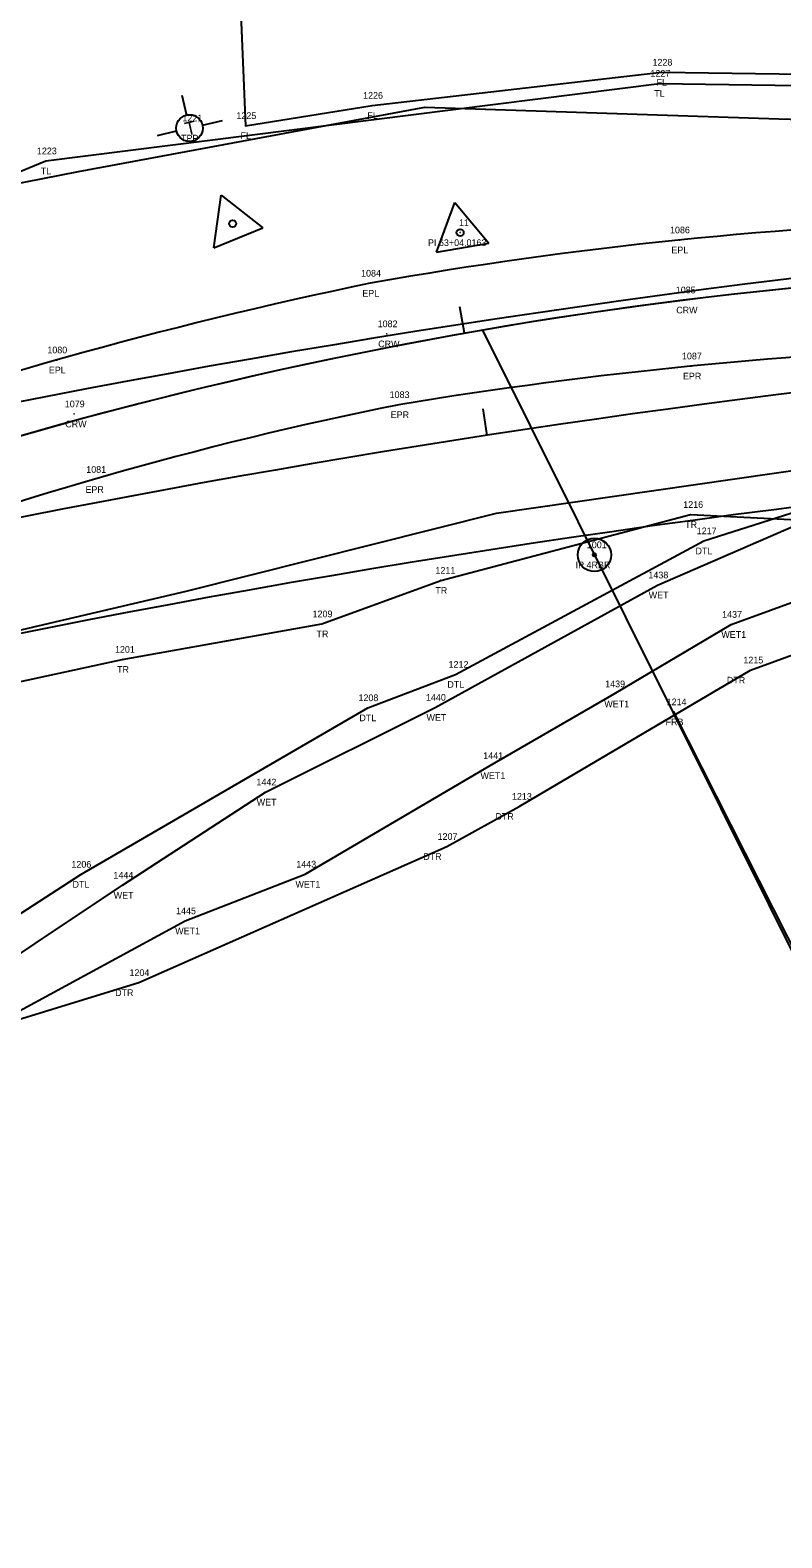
# Model space of a CAD drawing. Extents: x 1964982 to 1970527, y 1116335 to 1119906.
# Drawn here: x 1967915.5 to 1968028, y 1117741.3 to 1117966.8 of the extents above; entities that cross this region are included whole.
import ezdxf

# ---------------------------------------------------------------- set-up
doc = ezdxf.new("R2010")
doc.units = 0
for name, color, linetype in [('RD_EX_DV_Prop', 7, 'Continuous'), ('RD_EX_DV_Prop_txCode', 7, 'Continuous'), ('RD_EX_DV_PropPin', 7, 'Continuous'), ('RD_EX_Fence_Other', 7, 'Continuous'), ('RD_EX_Fence_Other_txCode', 7, 'Continuous'), ('RD_EX_H2O', 7, 'Continuous'), ('RD_EX_H2O_txCode', 7, 'Continuous'), ('RD_EX_H2O_WetLd', 7, 'Continuous'), ('RD_EX_H2O_WetLd_txCode', 7, 'Continuous'), ('RD_EX_Road', 7, 'Continuous'), ('RD_EX_Road_txCode', 7, 'Continuous'), ('RD_EX_RW', 7, 'Continuous'), ('RD_EX_UT', 7, 'Continuous'), ('RD_EX_UT_txCode', 7, 'Continuous'), ('RD_EX_VEG', 7, 'Continuous'), ('RD_EX_VEG_txCode', 7, 'Continuous'), ('RD_HC_CL', 7, 'Continuous'), ('RD_HC_CL_Rel', 7, 'Continuous'), ('RD_HC_Data', 7, 'Continuous'), ('RD_HC_Data_Rel', 7, 'Continuous'), ('RD_HC_Data_Tic', 7, 'Continuous'), ('RD_HC_Data_Tic_Rel', 7, 'Continuous'), ('RD_HC_txCode', 7, 'Continuous'), ('RD_PD_Bridge', 7, 'Continuous'), ('RD_SMD_Locator', 7, 'Continuous'), ('RD_SMD_Misc', 7, 'Continuous')]:
    doc.layers.add(name, color=color, linetype=linetype)

msp = doc.modelspace()

# ---------------------------------------------------------------- linework, layer by layer
at = {"layer": 'RD_EX_DV_Prop'}
msp.add_line((1967983.2, 1117921.94), (1968204.25, 1117478.1), dxfattribs=at)
msp.add_arc((1968094.39, 1117277.53), 653.93, 87.72663, 109.21172, dxfattribs=at)
at = {"layer": 'RD_EX_DV_PropPin'}
for radius in [2.5, 0.25]:
    msp.add_circle((1967999.94, 1117888.32), radius, dxfattribs=at)
at = {"layer": 'RD_EX_Fence_Other'}
msp.add_line((1968047.83, 1117793.64), (1968011.81, 1117864.83), dxfattribs=at)
msp.add_lwpolyline([(1967945.93, 1117995.37), (1967947.71, 1117952.52), (1967966.69, 1117955.54), (1968009.98, 1117960.51), (1968062.77, 1117959.8), (1968105.6, 1117961.86), (1968158.55, 1117958.33), (1968214.15, 1117955.95), (1968422.33, 1117947.89), (1968537.53, 1117942.88)], dxfattribs=at)
at = {"layer": 'RD_EX_H2O'}
for points in [[(1967869.1, 1117825.19), (1967872.82, 1117824.49), (1967892.16, 1117820.53), (1967923.08, 1117840.53), (1967966.02, 1117865.44), (1967979.17, 1117870.44), (1968016.32, 1117890.41), (1968058.49, 1117903.84)], [(1967873.55, 1117813.3), (1967887.27, 1117810.69), (1967931.74, 1117824.33), (1967977.85, 1117844.69), (1967988.67, 1117850.69), (1968023.3, 1117871.08), (1968058.02, 1117883.74)]]:
    msp.add_lwpolyline(points, dxfattribs=at)
at = {"layer": 'RD_EX_H2O_WetLd'}
for points in [[(1967871.9, 1117823.22), (1967882.77, 1117820.95), (1967892.49, 1117817.57), (1967903.12, 1117821.47), (1967929.31, 1117838.9), (1967950.71, 1117852.83), (1967976.12, 1117865.5), (1968009.37, 1117883.81), (1968032.7, 1117893.9)], [(1967873.8, 1117813.35), (1967880.72, 1117811.81), (1967886.54, 1117810.11), (1967895.47, 1117810.58), (1967906.3, 1117816.05), (1967938.67, 1117833.57), (1967956.67, 1117840.55), (1967984.36, 1117856.79), (1968002.89, 1117867.52), (1968020.4, 1117877.91), (1968037.49, 1117884.16)]]:
    msp.add_lwpolyline(points, dxfattribs=at)
at = {"layer": 'RD_EX_Road'}
for centre, radius, start, end in [((1968075.08, 1117320.65), 617.93, 91.49649, 100.12953), ((1968104.91, 1117261.07), 682.09, 101.71624, 109.63962), ((1968080.71, 1117246.52), 673.31, 91.83702, 99.40571), ((1968080.62, 1117362.97), 558.74, 101.3479, 110.7006)]:
    msp.add_arc(centre, radius, start, end, dxfattribs=at)
at = {"layer": 'RD_EX_RW'}
for points in [[(1967870.55, 1117935.43), (1967922.73, 1117945.65), (1967974.54, 1117955.28), (1968027.54, 1117953.56), (1968051.22, 1117952.87), (1968071.89, 1117951.65), (1968079.5, 1117951.05), (1968130.65, 1117948.99), (1968180.67, 1117948.41), (1968230.65, 1117947.05), (1968280.63, 1117945.53), (1968330.61, 1117944.01), (1968380.59, 1117942.48), (1968430.57, 1117940.91), (1968480.53, 1117939.07), (1968530.5, 1117937.23), (1968580.42, 1117934.25)], [(1967708.81, 1117795.77), (1967892.14, 1117871.97), (1967938.86, 1117882.89), (1967985.28, 1117894.57), (1968032.7, 1117901.37), (1968057.25, 1117897.44), (1968077.07, 1117897.99), (1968080.67, 1117898.09), (1968128.68, 1117899.27), (1968178.72, 1117899.38), (1968228.72, 1117898.21), (1968278.7, 1117896.78), (1968328.69, 1117895.52), (1968378.71, 1117895.2), (1968428.73, 1117894.55), (1968478.64, 1117891.45), (1968528.56, 1117888.35), (1968578.59, 1117888.04)]]:
    msp.add_lwpolyline(points, dxfattribs=at)
at = {"layer": 'RD_EX_UT'}
for p, q in [((1967938.2, 1117957.1), (1967938.89, 1117954.11)), ((1967941.29, 1117952.62), (1967944.28, 1117953.31)), ((1967934.53, 1117951.07), (1967937.39, 1117951.73))]:
    msp.add_line(p, q, dxfattribs=at)
msp.add_circle((1967939.34, 1117952.16), 2, dxfattribs=at)
at = {"layer": 'RD_EX_VEG'}
for points in [[(1967422.03, 1117809.72), (1967453.38, 1117748.92), (1967559.8, 1117796.17), (1967844.47, 1117917.07), (1967917.86, 1117947.25), (1968009.67, 1117958.84), (1968061.48, 1117958.08), (1968105.8, 1117963.33), (1968158.86, 1117956.79), (1968212.37, 1117954.08), (1968423.16, 1117946.63), (1968536.42, 1117942.26)], [(1967303.54, 1117601.01), (1967338.99, 1117640.22), (1967353.28, 1117654.56), (1967394.76, 1117667.24), (1967484.61, 1117707.66), (1967711.58, 1117796.67), (1967890.09, 1117864.21), (1967929.29, 1117872.68), (1967959.15, 1117877.99), (1967976.93, 1117884.5), (1968014.32, 1117894.35), (1968104.14, 1117889.87), (1968155.31, 1117895.48), (1968209.85, 1117895.88), (1968320.55, 1117893.51), (1968423.04, 1117892.22), (1968529.15, 1117876.96)]]:
    msp.add_lwpolyline(points, dxfattribs=at)
at = {"layer": 'RD_HC_CL'}
msp.add_arc((1968094.39, 1117277.53), 653.93, 87.72663, 111.99584, dxfattribs=at)
at = {"layer": 'RD_HC_CL_Rel'}
msp.add_arc((1968232.57, 1116288.18), 1637.02, 87.72663, 111.99584, dxfattribs=at)
at = {"layer": 'RD_HC_Data'}
for p, q in [((1967976.32, 1117933.58), (1967979.05, 1117941.04)), ((1967979.05, 1117941.04), (1967984.14, 1117934.94)), ((1967976.32, 1117933.58), (1967984.14, 1117934.94))]:
    msp.add_line(p, q, dxfattribs=at)
msp.add_circle((1967979.84, 1117936.52), 0.529, dxfattribs=at)
at = {"layer": 'RD_HC_Data_Rel'}
for p, q in [((1967942.98, 1117934.26), (1967944.09, 1117942.13)), ((1967944.09, 1117942.13), (1967950.34, 1117937.23)), ((1967942.98, 1117934.26), (1967950.34, 1117937.23))]:
    msp.add_line(p, q, dxfattribs=at)
msp.add_circle((1967945.8, 1117937.87), 0.529, dxfattribs=at)
at = {"layer": 'RD_HC_Data_Tic'}
msp.add_line((1967980.52, 1117921.47), (1967979.82, 1117925.41), dxfattribs=at)
at = {"layer": 'RD_HC_Data_Tic_Rel'}
msp.add_line((1967983.9, 1117906.2), (1967983.29, 1117910.16), dxfattribs=at)
at = {"layer": 'RD_PD_Bridge'}
for radius in [1654.02, 1620.02]:
    msp.add_arc((1968232.57, 1116288.18), radius, 96.21741, 110.04242, dxfattribs=at)
at = {"layer": 'RD_SMD_Locator'}
for centre in [(1968009.98, 1117960.51), (1968009.67, 1117958.84), (1967966.69, 1117955.54), (1967947.71, 1117952.52), (1967917.86, 1117947.25), (1967979.84, 1117936.52), (1968012.66, 1117935.42), (1967966.4, 1117928.95), (1968013.49, 1117926.44), (1967968.89, 1117921.38), (1967919.49, 1117917.47), (1968014.42, 1117916.56), (1967922.07, 1117909.4), (1967970.68, 1117910.78), (1967924.99, 1117899.59), (1968014.32, 1117894.35), (1968016.32, 1117890.41), (1967976.93, 1117884.5), (1968009.37, 1117883.81), (1967959.15, 1117877.99), (1968020.4, 1117877.91), (1967929.29, 1117872.68), (1968023.3, 1117871.08), (1967979.17, 1117870.44), (1968002.89, 1117867.52), (1967966.02, 1117865.44), (1967976.12, 1117865.5), (1968011.81, 1117864.83), (1967984.36, 1117856.79), (1967950.71, 1117852.83), (1967988.67, 1117850.69), (1967977.85, 1117844.69), (1967923.08, 1117840.53), (1967956.67, 1117840.55), (1967929.31, 1117838.9), (1967938.67, 1117833.57), (1967931.74, 1117824.33)]:
    msp.add_circle(centre, 0.001, dxfattribs=at)

# ---------------------------------------------------------------- texts
at = {"layer": 'RD_EX_DV_Prop_txCode'}
for s, p in [('1001', (1967998.8, 1117889.32)), ('IP 4RBR', (1967997.13, 1117886.32))]:
    msp.add_text(s, height=1, dxfattribs=at).set_placement(p)
at = {"layer": 'RD_EX_Fence_Other_txCode'}
for s, p in [('1228', (1968008.63, 1117961.51)), ('FL', (1968009.24, 1117958.51)), ('1226', (1967965.32, 1117956.54)), ('1225', (1967946.36, 1117953.52)), ('FL', (1967965.96, 1117953.54)), ('FL', (1967946.98, 1117950.52)), ('1214', (1968010.75, 1117865.83)), ('FRB', (1968010.59, 1117862.83))]:
    msp.add_text(s, height=1, dxfattribs=at).set_placement(p)
at = {"layer": 'RD_EX_H2O_txCode'}
for s, p in [('1217', (1968015.25, 1117891.41)), ('DTL', (1968015.07, 1117888.41)), ('1212', (1967978.11, 1117871.44)), ('1215', (1968022.23, 1117872.08)), ('DTL', (1967977.93, 1117868.44)), ('DTR', (1968019.76, 1117869.08)), ('1208', (1967964.63, 1117866.44)), ('DTL', (1967964.77, 1117863.44)), ('1213', (1967987.6, 1117851.69)), ('DTR', (1967985.13, 1117848.69)), ('1207', (1967976.47, 1117845.69)), ('1206', (1967921.67, 1117841.53)), ('DTR', (1967974.32, 1117842.69)), ('DTL', (1967921.84, 1117838.53)), ('1204', (1967930.36, 1117825.33)), ('DTR', (1967928.21, 1117822.33))]:
    msp.add_text(s, height=1, dxfattribs=at).set_placement(p)
at = {"layer": 'RD_EX_H2O_WetLd_txCode'}
for s, p in [('1438', (1968008.02, 1117884.81)), ('WET', (1968008.06, 1117881.81)), ('1437', (1968019.05, 1117878.91)), ('WET1', (1968018.93, 1117875.91)), ('1439', (1968001.55, 1117868.52)), ('1440', (1967974.73, 1117866.5)), ('WET1', (1968001.42, 1117865.52)), ('WET', (1967974.81, 1117863.5)), ('1441', (1967983.3, 1117857.79)), ('WET1', (1967982.89, 1117854.79)), ('1442', (1967949.36, 1117853.83)), ('WET', (1967949.4, 1117850.83)), ('1443', (1967955.32, 1117841.55)), ('1444', (1967927.96, 1117839.9)), ('WET1', (1967955.2, 1117838.55)), ('WET', (1967928, 1117836.9)), ('1445', (1967937.33, 1117834.57)), ('WET1', (1967937.2, 1117831.57))]:
    msp.add_text(s, height=1, dxfattribs=at).set_placement(p)
at = {"layer": 'RD_EX_Road_txCode'}
for s, p in [('1086', (1968011.25, 1117936.42)), ('EPL', (1968011.46, 1117933.42)), ('1084', (1967965.02, 1117929.95)), ('EPL', (1967965.2, 1117926.95)), ('1080', (1967918.07, 1117918.47)), ('1087', (1968013.04, 1117917.56)), ('EPL', (1967918.29, 1117915.47)), ('EPR', (1968013.19, 1117914.56)), ('1083', (1967969.29, 1117911.78)), ('EPR', (1967969.45, 1117908.78)), ('1081', (1967923.89, 1117900.59)), ('EPR', (1967923.77, 1117897.59))]:
    msp.add_text(s, height=1, dxfattribs=at).set_placement(p)
at = {"layer": 'RD_EX_UT'}
msp.add_text('T', height=2, rotation=12.9436, dxfattribs=at).set_placement((1967938.92, 1117950.99))
at = {"layer": 'RD_EX_UT_txCode'}
for s, p in [('1221', (1967938.28, 1117953.16)), ('TPP', (1967938.07, 1117950.16))]:
    msp.add_text(s, height=1, dxfattribs=at).set_placement(p)
at = {"layer": 'RD_EX_VEG_txCode'}
for s, p in [('1227', (1968008.32, 1117959.84)), ('TL', (1968008.9, 1117956.84)), ('1223', (1967916.51, 1117948.25)), ('TL', (1967917.08, 1117945.25)), ('1216', (1968013.23, 1117895.35)), ('TR', (1968013.52, 1117892.35)), ('1211', (1967976.15, 1117885.5)), ('TR', (1967976.13, 1117882.5)), ('1209', (1967957.76, 1117878.99)), ('TR', (1967958.35, 1117875.99)), ('1201', (1967928.19, 1117873.68)), ('TR', (1967928.5, 1117870.68))]:
    msp.add_text(s, height=1, dxfattribs=at).set_placement(p)
at = {"layer": 'RD_HC_txCode'}
for s, p in [('11', (1967979.67, 1117937.52)), ('PI 63+04.0163', (1967975.04, 1117934.52))]:
    msp.add_text(s, height=1, dxfattribs=at).set_placement(p)
at = {"layer": 'RD_SMD_Misc'}
for s, p in [('1085', (1968012.11, 1117927.44)), ('CRW', (1968012.18, 1117924.44)), ('1082', (1967967.5, 1117922.38)), ('CRW', (1967967.58, 1117919.38)), ('1079', (1967920.68, 1117910.4)), ('CRW', (1967920.75, 1117907.4))]:
    msp.add_text(s, height=1, dxfattribs=at).set_placement(p)

doc.saveas('drawing.dxf')
